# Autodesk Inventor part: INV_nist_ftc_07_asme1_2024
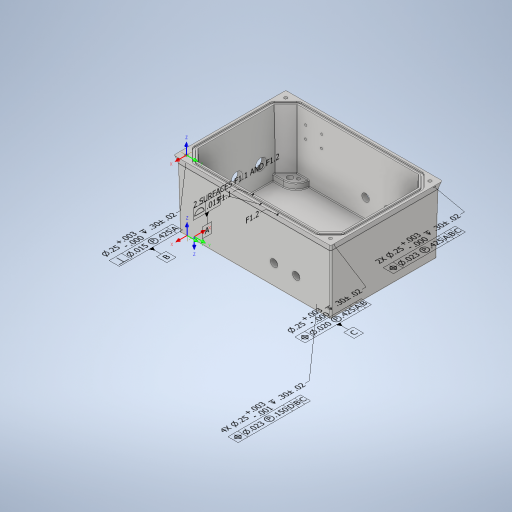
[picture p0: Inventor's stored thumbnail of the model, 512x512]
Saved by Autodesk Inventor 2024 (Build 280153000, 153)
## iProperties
Created: 2016-11
Part Number: INV_nist_ftc_07_asme1_2024
Material: Generic
Document SubType Name: Modeling
Designer: t_liuje
Density: 1 g/cm^3
Appearance: Default
Author: t_liuje
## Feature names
1. Extrusion1
2. FaceDraft1
3. Extrusion2
4. FaceDraft2
5. Extrusion3
6. Extrusion4
7. Extrusion5
8. Hole2
9. Hole4
10. Hole5
11. Mirror1
12. Mirror2
13. Extrusion6
14. FaceDraft3
15. FaceDraft4
16. Fillet1
17. Fillet2
18. Sweep1
19. Fillet3
20. Extrusion7
21. Extrusion8
## Parameters: d0 = 304.8 mm, d1 = 215.9 mm, d2 = 120.65 mm, d3 = 0, d4 = 12.7 mm, d5 = 0, d6 = -5.08 mm, d7 = 281.94 mm, d8 = 193.04 mm, d12 = 21.336 mm, d13 = 21.336 mm, d14 = 21.336 mm, d15 = 21.336 mm, d16 = 21.336 mm, d17 = 21.336 mm, d18 = 21.336 mm, d19 = 21.336 mm, d20 = 0, d21 = 0, d22 = 45.72 mm, d23 = 25.4 mm, d24 = 25.4 mm, d25 = 45.72 mm, d26 = 45.72 mm, d27 = 45.72 mm, d28 = 25.4 mm, d29 = 25.4 mm, d30 = 25.4 mm, d31 = 25.4 mm, d32 = 11.43 mm, d33 = 0, d34 = -1 deg, d35 = -15 deg, d38 = 25.4 mm, d39 = 25.4 mm, d46 = 2.54 mm, d47 = 0, d57 = 10.7442 mm, d59 = 10.7442 mm, d60 = 19.1516 mm, d61 = 19.1516 mm, d62 = 10.7442 mm, d63 = 10.7442 mm, d64 = 19.1516 mm, d65 = 11.43 mm, d66 = 31.75 mm, d67 = 7.1374 mm, d68 = 19.05 mm, d69 = 11.1252 mm, d70 = 7.62 mm, d71 = 82 deg, d72 = 25.4 mm, d73 = 0, d74 = 19.1516 mm, d84 = 215.9 mm, d85 = 304.8 mm, d86 = 281.94 mm, d87 = 11.43 mm, d88 = 11.43 mm, d89 = 17.5514 mm, d90 = 42.3926 mm, d91 = 6.35 mm, d92 = 19.05 mm, d93 = 11.1252 mm, d94 = 6.35 mm, d95 = 82 deg, d96 = 7.62 mm, d97 = 0, d98 = 12.7 mm, d99 = 12.7 mm, d100 = 6.35 mm, d101 = 19.05 mm, d102 = 11.1252 mm, d103 = 6.35 mm, d104 = 82 deg, d105 = 7.62 mm, d106 = 0, d107 = 15.0876 mm, d108 = 43.9928 mm, d109 = 42.5958 mm, d110 = 67.437 mm, d111 = 42.5958 mm, d112 = 2.54 mm, d113 = 0, d114 = 1 deg, d115 = 1 deg, d116 = 3.2004 mm, d119 = 1.524 mm, d120 = 3.048 mm, d121 = 0, d122 = 0, d124 = 91 deg, d125 = 2.6416 mm, d126 = 91 deg, d127 = 4.80061 mm, d128 = 0.381 mm, d131 = 47.625 mm, d132 = 47.625 mm, d133 = 107.95 mm, d134 = 45.0088 mm, d135 = 45.0088 mm, d136 = 45.0088 mm, d137 = 25.4 mm, d138 = 0, d139 = 31.75 mm, d140 = 24.13 mm, d141 = 4.3942 mm, d142 = 14.1986 mm, d143 = 14.1986 mm, d144 = 24.13 mm, d145 = 31.75 mm, d146 = 49.276 mm, d147 = 49.276 mm, d148 = 43.9928 mm, d149 = 42.3418 mm, d150 = 42.3418 mm, d151 = 89.4334 mm, d152 = 15.0876 mm, d153 = 25.4 mm, d154 = 0, d221 = 22.225 mm, d304 = 22.5 deg, d305 = 45 deg, d306 = 25.4 mm, d346 = 0, d347 = 0, d348 = 0, d349 = 90 deg, d350 = 0, d351 = 90 deg, d352 = 12.7 mm, d353 = 0, d354 = 0, d355 = 90 deg, d356 = 0, d357 = 90 deg, d374 = 0, d375 = 0, d376 = 0, d377 = -90 deg, d378 = 0, d379 = 90 deg, d155 = 9.93178 mm, d156 = 4.70171 mm, d157 = 9.95259 mm, d158 = 6.59847 mm, d272 = 8.35297 mm, d273 = 6.29321 mm, d274 = 1.524 mm, d275 = 0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
